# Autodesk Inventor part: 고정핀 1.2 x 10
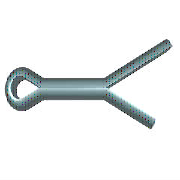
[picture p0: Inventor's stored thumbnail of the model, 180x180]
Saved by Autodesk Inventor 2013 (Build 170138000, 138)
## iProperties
IsCustomPart: 1
Created: 2012-02
Part Number: 고정핀 1.2 x 10
Material: 강철
Description: 분할 핀
Document SubType Name: Modeling
Standard: ISO 1234
Designer: test
Standard Revision: Second edition 1997-11-01
Standards Organization: ISO
Language: ko-KR
Size Designation: 1.2 x 10
Categories: <MemberInstance><Categories><Category DisplayName="조임쇠" InternalName="e4da775c-781d-43d5-af7c-5136215cf5a6" Mnemonic="FSTN"><Category DisplayName="핀" InternalNa
Density: 7.85 g/cm^3
Author: test
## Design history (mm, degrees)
sketch "스케치1"
  geometry: L1 (0, 0.5)-(5, 0.5); L2 (0, -0.5)-(5, -0.5); L3 (5, 0.5)-(10, 2.416); L4 (10, 2.416)-(10.167, 1.98); L5 (10.167, 1.98)-(5, 0); L6 (5, 0)-(12.667, -2.937); L7 (12.667, -2.937)-(12.5, -3.373); L8 (12.5, -3.373)-(5, -0.5); L9 (0, 0)-(-1.875, -0.484); L10 (0, 0)-(-1.875, 0.484); L11 (0, 0.5)-(0, -0.5); L12 (0, 0.5)-(-1.742, 0.966); L13 (0, -0.5)-(-1.742, -0.966); L14 (-3, 0)-(5, 0); L15 (5, 0.5)-(5, -0.5); A1 r 1 centre (-2, 0) between (-1.742, 0.966) and (-1.742, -0.966); A2 r 0.5 centre (-2, 0) between (-1.875, 0.484) and (-1.875, -0.484); 1 further point
  constraints: 30 end point, 5 point on circle, 4 parallel, 4 perpendicular, 4 point on line, 4 tangent, 2 centre point, 2 midpoint, 1 coincident, 1 horizontal
  dimensions: "d0" = 5 distance of L1.start L1.end (= MSIAB); "d1" = 10 horizontal distance of L1.start L3.end (= SNLG); "d2" = 159.037 deg angle of L1 L3; "d3" = 159.037 deg angle of L2 L8; "d4" = 2.5 horizontal distance of L3.end L7.end (= LGDIF); "d5" = 0.5 radius of A2 (= -0.5 x SNND1 + 0.5 x KBR); "d6" = 1 radius of A1 (= 0.5 x KBR); "d7" = 0.5 distance from line of L1 L9.start (= 0.5 x SNND1); "d8" = 0.5 distance between parallel lines of L2 L14 (= 0.5 x SNND1); "d9" = 2 distance from line of L11 A1.centre (= KOL - 0.5 x KBR)
extrude "본체" new body sketch "스케치1" stored distance "d10" = 1 (= SNND1); taper "d11" = 0 deg
workaxis "Work Axis1"
workplane "Work Plane1"
workplane "Work Plane3"
body "Solid1"
fillet "모깎기" dims "d12" = 0.35 (= 0.35 x SNND1)
other parameters: "SNND" = 1.2 [user parameter], "SNLG" = 10 [user parameter; used in 1 equation term], "SNND1" = 1 [user parameter; used in 5 equation terms], "KBR" = 2 [user parameter; used in 3 equation terms], "KOL" = 3 [user parameter; used in 1 equation term], "LGDIF" = 2.5 [user parameter; used in 1 equation term], "MSIAB" = 5 [user parameter; used in 1 equation term], "d15" = 0, "d16" = 0, "d17" = 0, "NNDMAX" = 5.5 [user parameter], "DSH" = 2.6 [user parameter], "NNDMIN" = 4.5 [user parameter]
